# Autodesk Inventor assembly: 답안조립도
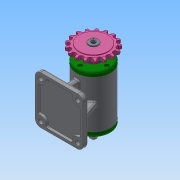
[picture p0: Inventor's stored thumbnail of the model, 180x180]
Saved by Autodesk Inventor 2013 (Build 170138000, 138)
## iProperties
Created: 2019-06
Part Number: 답안조립도
Document SubType Name: Assembly
Designer: Administrator
Author: Administrator
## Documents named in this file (11)
- C:\Users\Administrator\Desktop\490604V1018\답안조립도.iam
- C:\Users\Administrator\Desktop\490604V1018\본체.ipt
- C:\Users\Administrator\Desktop\490604V1018\베어링 6203.ipt
- C:\Users\Administrator\Desktop\490604V1018\볼트 M4.ipt
- C:\Users\Administrator\Desktop\490604V1018\스프로킷.ipt
- C:\Users\Administrator\Desktop\490604V1018\스프링와셔.ipt
- C:\Users\Administrator\Desktop\490604V1018\오일 실 17 30 5.ipt
- C:\Users\Administrator\Desktop\490604V1018\축.ipt
- C:\Users\Administrator\Desktop\490604V1018\커버.ipt
- C:\Users\Administrator\Desktop\490604V1018\키 4x4x12.ipt
- C:\Users\Administrator\Desktop\490604V1018\평와셔.ipt
